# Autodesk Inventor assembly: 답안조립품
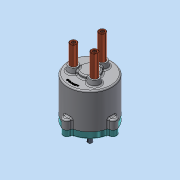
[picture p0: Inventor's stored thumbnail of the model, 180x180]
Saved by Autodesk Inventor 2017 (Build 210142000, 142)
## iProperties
Part Number: 답안조립품
Material: 일반
Document SubType Name: Assembly
Designer: MRC
Mass: 1236.64 g
Surface Area: 1770.13 cm^2
Volume: 433.789 cm^3
Density: 2.85078 g/cm^3
Author: MRC
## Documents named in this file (14)
- C:\Users\MRC\Desktop\610708V1010\답안조립품.iam
- C:\Users\MRC\Desktop\610708V1010\본체.ipt
- C:\Users\MRC\Desktop\610708V1010\가변스프링1.ipt
- C:\Users\MRC\Desktop\610708V1010\가변스프링2.ipt
- C:\Users\MRC\Desktop\610708V1010\가변스프링3.ipt
- C:\Users\MRC\Desktop\610708V1010\멈춤링 10 x 1.ipt
- C:\Users\MRC\Desktop\610708V1010\멈춤링 22 x 1.2.ipt
- C:\Users\MRC\Desktop\610708V1010\메인 축.ipt
- C:\Users\MRC\Desktop\610708V1010\베어링 NA 4900.ipt
- C:\Users\MRC\Desktop\610708V1010\볼트 M5.ipt
- C:\Users\MRC\Desktop\610708V1010\슬라이드 축.ipt
- C:\Users\MRC\Desktop\610708V1010\오일실.ipt
- C:\Users\MRC\Desktop\610708V1010\커버.ipt
- C:\Users\MRC\Desktop\610708V1010\판캠.ipt
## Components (3 placed, 3 different names)
1. 가변스프링1:1
2. 가변스프링2:1
3. 가변스프링3:1
